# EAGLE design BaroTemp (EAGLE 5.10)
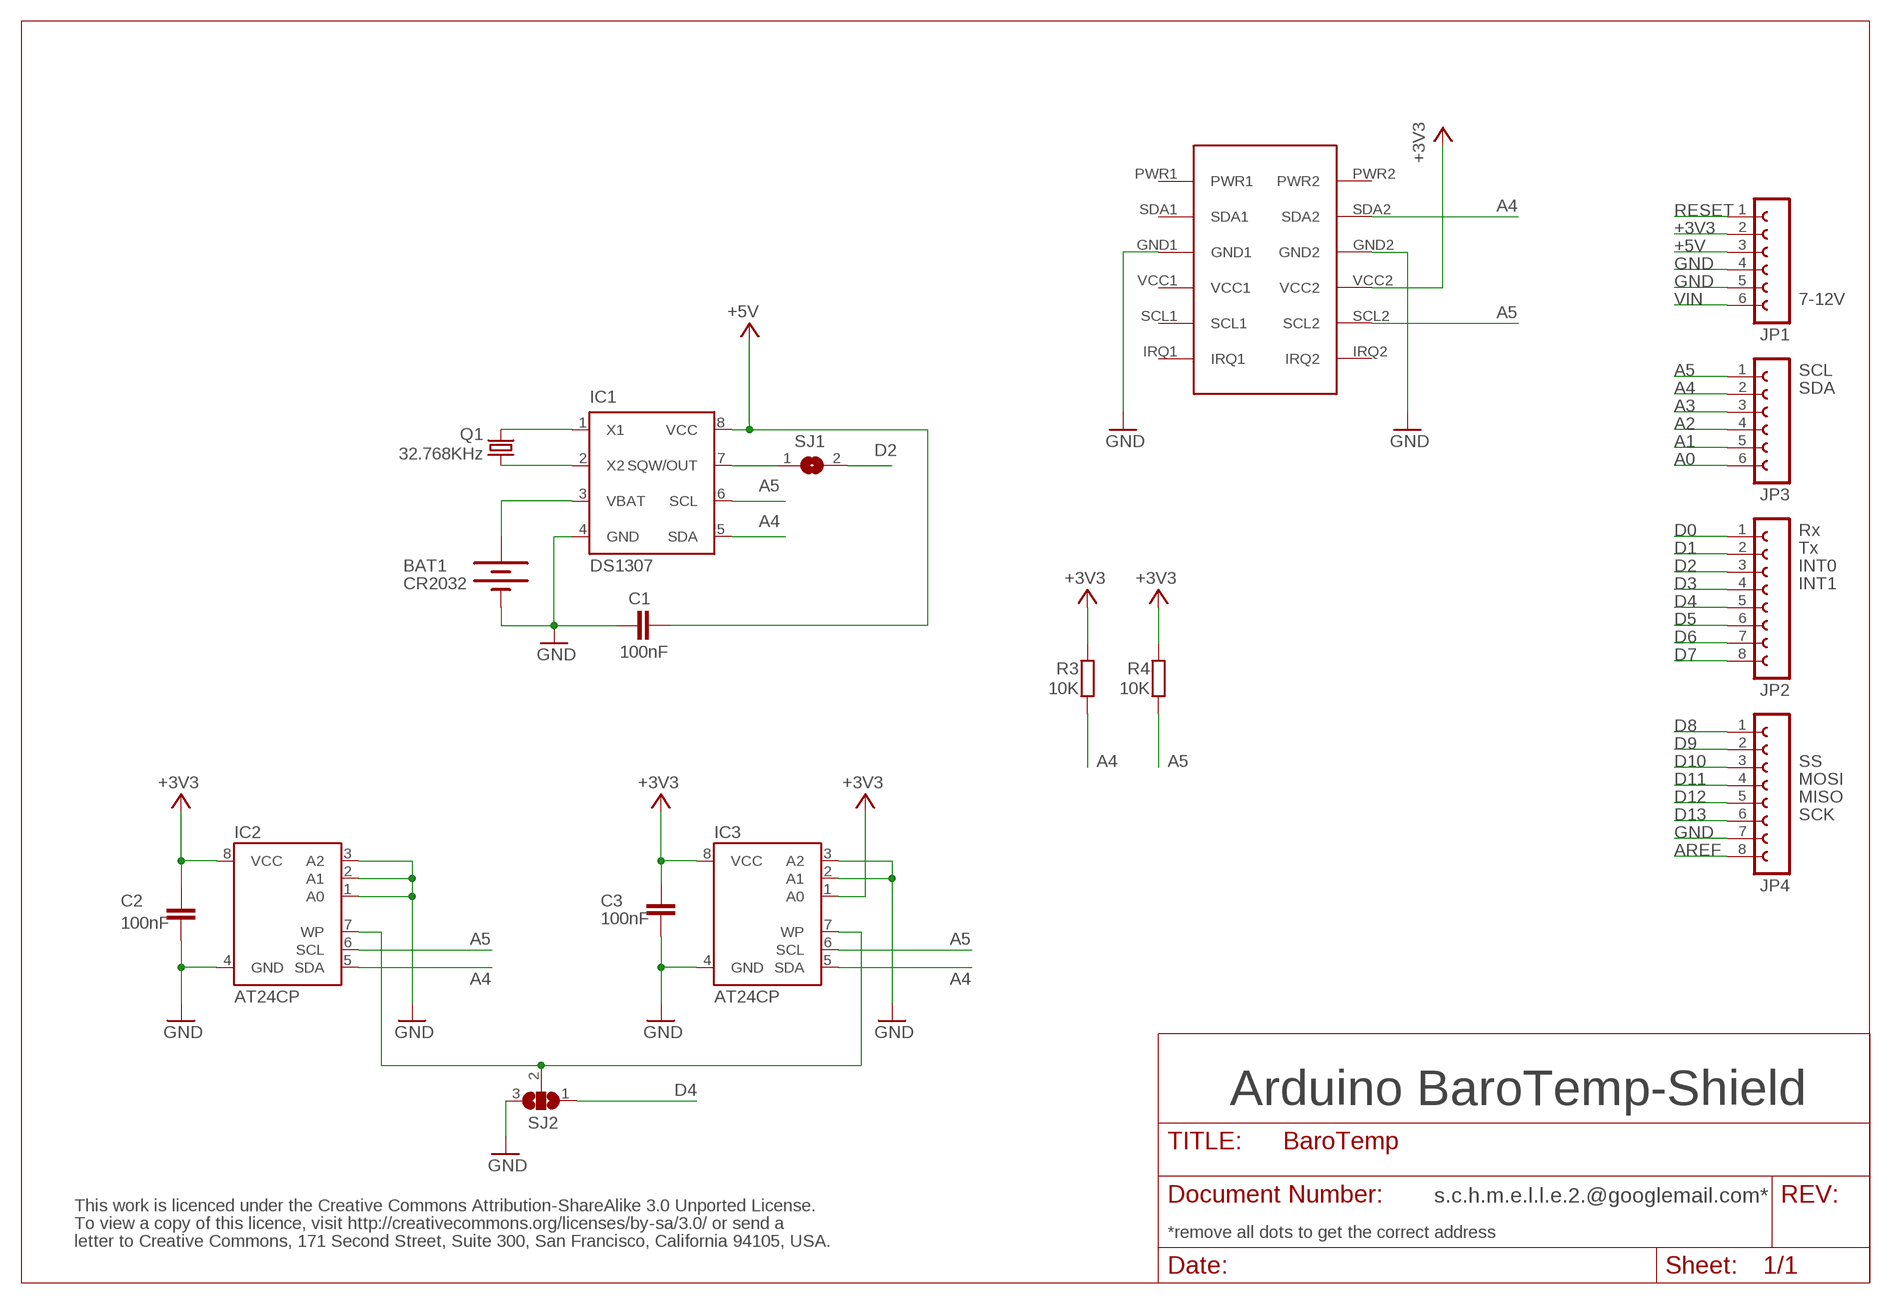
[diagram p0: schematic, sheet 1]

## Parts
BAT1  CR2032  BATTERY20PTH  [BATTCOM_20MM_PTH]
C1  100nF  C-EU050-025X075  [C050-025X075]
C2  100nF  C-EU050-025X075  [C050-025X075]
C3  100nF  C-EU050-025X075  [C050-025X075]
IC1  DS1307  [DIL08]
IC2  AT24CP  [DIL08]
IC3  AT24CP  [DIL08]
JP1  FE06-1  [FE06]
JP2  FE08-1  [FE08]
JP3  FE06-1  [FE06]
JP4  FE08-1  [FE08]
Q1  32.768KHz  CRYSTALTC26V  [TC26V]
R3  10K  R-EU_0207/10  [0207/10]
R4  10K  R-EU_0207/10  [0207/10]
SJ1  SJ  [SJ]
SJ2  SJ2W  [SJ_2]
U$1  PRESSURE_PLUG  [BMP085-BO]

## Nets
+3V3: C2.2 C3.2 IC2.8(VCC) IC3.1(A0) IC3.8(VCC) JP1.2 R3.2 R4.2 U$1.VCC2
+5V: C1.2 IC1.8(VCC) JP1.3
A0: JP3.6
A1: JP3.5
A2: JP3.4
A3: JP3.3
A4: IC1.5(SDA) IC2.5(SDA) IC3.5(SDA) JP3.2 R3.1 U$1.SDA2
A5: IC1.6(SCL) IC2.6(SCL) IC3.6(SCL) JP3.1 R4.1 U$1.SCL2
AREF: JP4.8
D0: JP2.1
D1: JP2.2
D2: JP2.3 SJ1.2
D3: JP2.4
D4: JP2.5 SJ2.1
D5: JP2.6
D6: JP2.7
D7: JP2.8
D8: JP4.1
D9: JP4.2
D10: JP4.3
D11: JP4.4
D12: JP4.5
D13: JP4.6
GND: BAT1.2(-) C1.1 C2.1 C3.1 IC1.4(GND) IC2.1(A0) IC2.2(A1) IC2.3(A2) IC2.4(GND) IC3.2(A1) IC3.3(A2) IC3.4(GND) JP1.4 JP1.5 JP4.7 SJ2.3 U$1.GND1 U$1.GND2
N$1: BAT1.1(+) IC1.3(VBAT)
N$3: IC2.7(WP) IC3.7(WP) SJ2.2
N$4: IC1.1(X1) Q1.2
N$6: IC1.2(X2) Q1.1
N$285: IC1.7(SQW/OUT) SJ1.1
RESET: JP1.1
VIN: JP1.6
Unconnected: U$1.IRQ1 U$1.IRQ2 U$1.SCL1 U$1.SDA1

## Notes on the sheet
- 7-12V
- SCL
- SDA
- Rx
- Tx
- INT0
- INT1
- SS
- MOSI
- MISO
- SCK
- Arduino BaroTemp-Shield
- s.c.h.m.e.l.l.e.2.@googlemail.com*
- This work is licenced under the Creative Commons Attribution-ShareAlike 3.0 Unported License.
- To view a copy of this licence, visit http://creativecommons.org/licenses/by-sa/3.0/ or send a
- *remove all dots to get the correct address
- letter to Creative Commons, 171 Second Street, Suite 300, San Francisco, California 94105, USA.

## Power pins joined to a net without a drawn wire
PWR1: U$1.PWR1
PWR2: U$1.PWR2
VCC1: U$1.VCC1

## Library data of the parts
BAT1 = SparkFun:BATTERY: Battery Holders
C1-C3 = resistor:C-EU: CAPACITOR, European symbol
IC1 = Peter-Privat:DS1307: I2C Serial RTC w/56 bytes battery backed RAM
IC2 IC3 = atmel:AT24C*: 2-wire serial EEPROM
JP1 JP3 = con-lsta:FE06-1: FEMALE HEADER
JP2 JP4 = con-lsta:FE08-1: FEMALE HEADER
Q1 = crystal:CRYSTAL: CRYSTAL
R3 R4 = resistor:R-EU_: RESISTOR, European symbol
SJ1 = jumper:SJ: SMD solder JUMPER
SJ2 = jumper:SJ2W: SMD solder JUMPER
U$1 = Peter-Privat:PRESSURE_PLUG: BMP085 Breakout Board von http://shop.jeelabs.com/products/pressure-plug

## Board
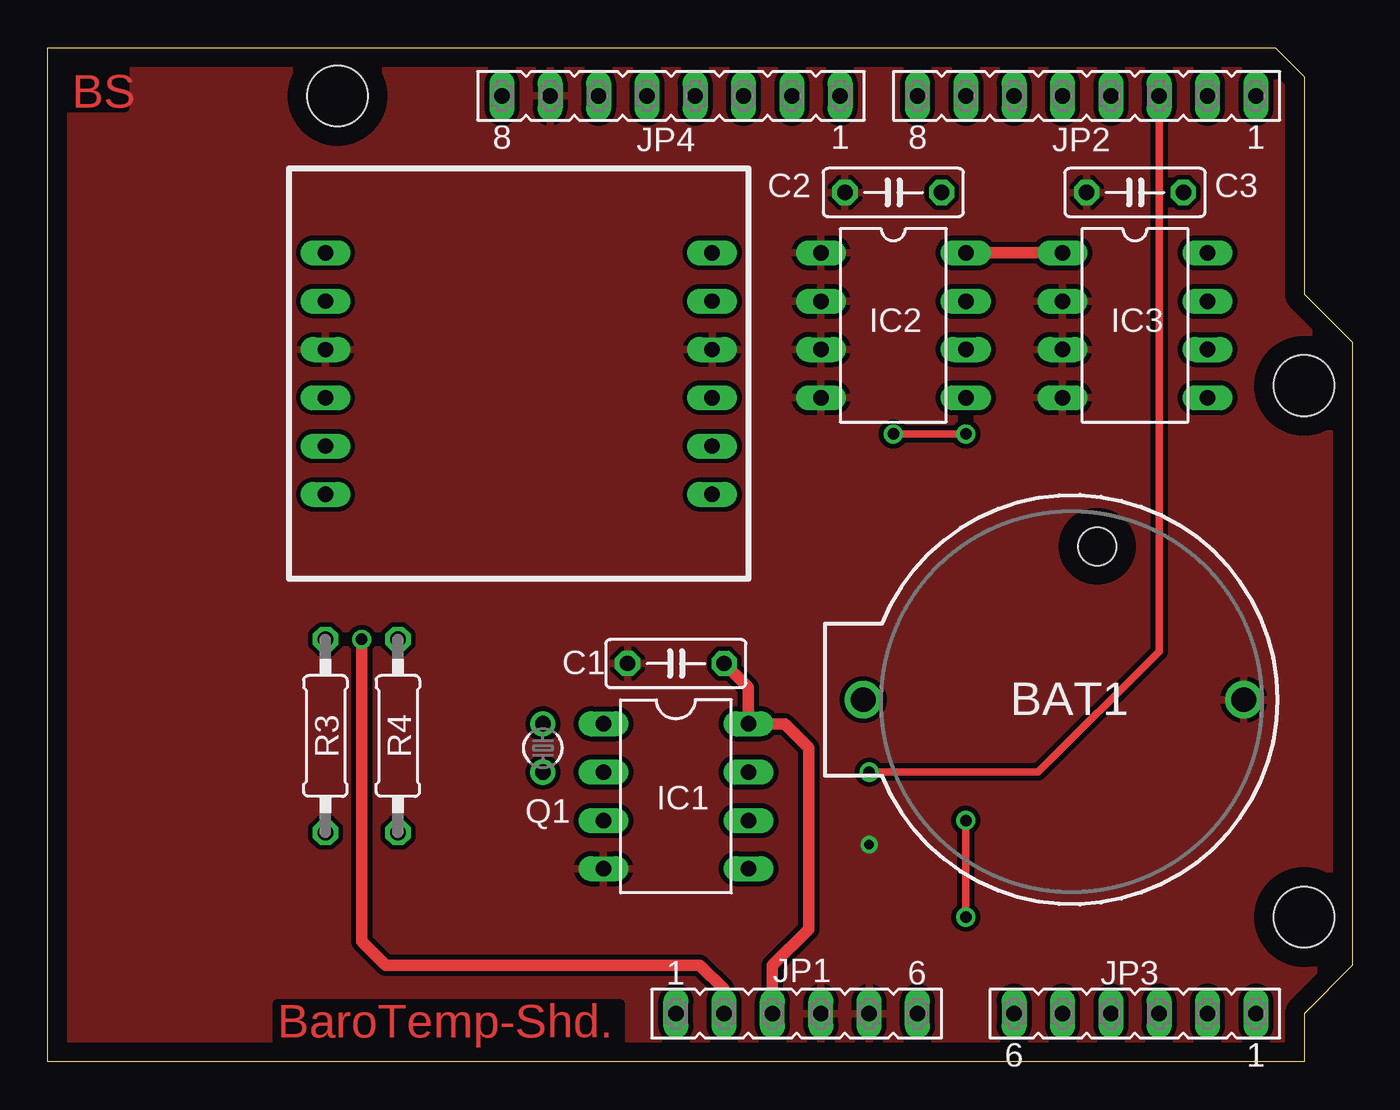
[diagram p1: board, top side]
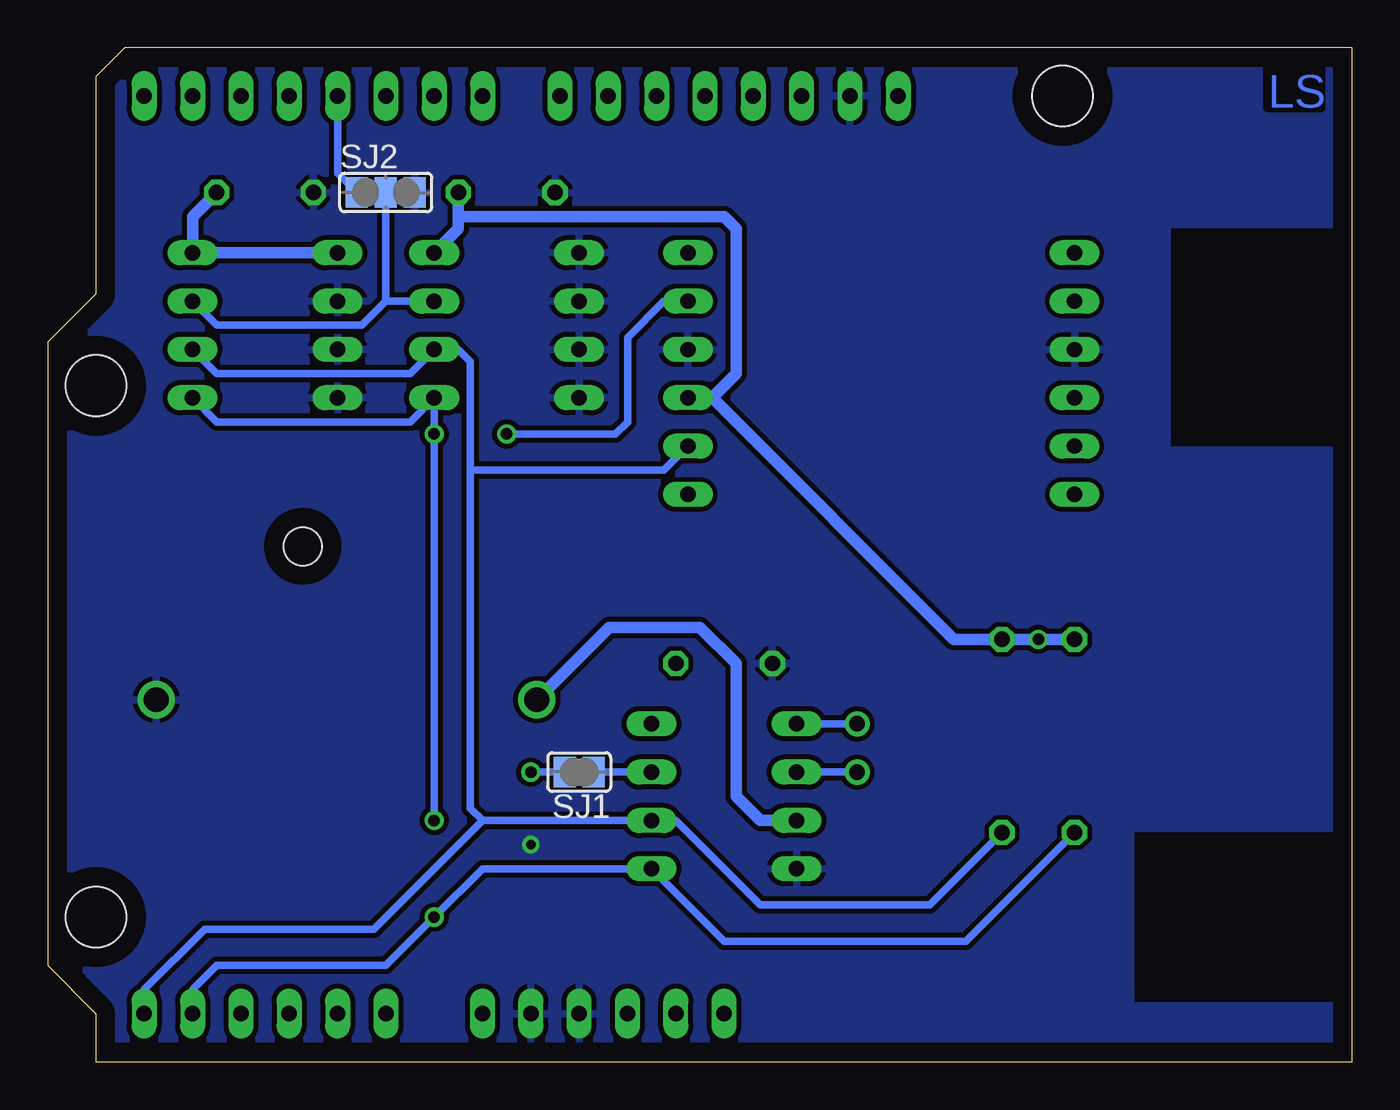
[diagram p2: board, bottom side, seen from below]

Size 68.58 x 53.34 mm. Coordinates in mm from the lower left corner, seen from the top.
Outline: 0,0 0,53.34 64.52,53.34 66.04,51.82 66.04,40.39 68.58,37.85 68.58,5.08 66.04,2.54 66.04,0 0,0
Copper layers (1*16): Top 0.035mm / dielectric 1.5mm / Bottom 0.035mm
Design rules "Bilex DRU": minimum track width 10mil, minimum drill 24mil, track to track 10mil, track to pad 10mil, pad to pad 10mil, via to via 10mil, smd to smd 10mil, copper to edge 40mil, drill to drill 8mil, minimum pad ring 10mil, minimum via ring 8mil, stop-mask expansion 4mil, vias tented up to drill 0mil, thermal gap 10mil
Holes 3.2 mm at 15.24,50.8 66.04,35.56 66.04,7.62
Holes 2 mm at 55.17,27.11
tKeepout: area 0,32.4 to 9.5,43.8; area 0,3.2 to 11.4,12.1
bKeepout: area 0,32.4 to 9.5,43.8; area 0,32.4 to 9.5,43.8; area 0,3.2 to 11.4,12.1
bRestrict: area 0,32.4 to 9.5,43.8; area 0,32.4 to 9.5,43.8; area 0,3.2 to 11.4,12.1

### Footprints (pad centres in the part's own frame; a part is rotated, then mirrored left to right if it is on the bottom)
BATTCOM_20MM_PTH = drill 1.3 round: 1 20,0; 2 0,0
C050-025X075 = drill 0.813 octagon: 1 -2.54,0; 2 2.54,0
DIL08 = drill 0.813 long: 1 -3.81,-3.81; 2 -1.27,-3.81; 3 1.27,-3.81; 4 3.81,-3.81; 5 3.81,3.81; 6 1.27,3.81; 7 -1.27,3.81; 8 -3.81,3.81
FE06 = drill 0.813 long: 1 -6.35,0; 2 -3.81,0; 3 -1.27,0; 4 1.27,0; 5 3.81,0; 6 6.35,0
FE08 = drill 0.813 long: 1 -8.89,0; 2 -6.35,0; 3 -3.81,0; 4 -1.27,0; 5 1.27,0; 6 3.81,0; 7 6.35,0; 8 8.89,0
TC26V = drill 0.813 round: 1 -1.27,0; 2 1.27,0
0207/10 = drill 0.813 octagon: 1 -5.08,0; 2 5.08,0
SJ = smd 1.168 x 1.6: 1 -0.762,0; 2 0.762,0
SJ_2 = smd 1.168 x 1.6: 1 -1.524,0; 2 0,0; 3 1.524,0
BMP085-BO = drill 0.8 long: GND1 -10.16,1.27; GND2 10.16,1.27; IRQ1 -10.16,-6.35; IRQ2 10.16,-6.35; PWR1 -10.16,6.35; PWR2 10.16,6.35; SCL1 -10.16,-3.81; SCL2 10.16,-3.81; SDA1 -10.16,3.81; SDA2 10.16,3.81; VCC1 -10.16,-1.27; VCC2 10.16,-1.27

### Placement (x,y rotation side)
BAT1  62.87,19.05 180 top
C1  33.02,20.95 0 top
C2  44.45,45.72 0 top
C3  57.15,45.72 0 top
IC1  33.02,13.97 270 top
IC2  44.45,38.73 270 top
IC3  57.15,38.73 270 top
JP1  39.37,2.54 0 top
JP2  54.61,50.8 180 top
JP3  57.15,2.54 180 top
JP4  32.77,50.8 180 top
Q1  26.04,16.51 90 top
R3  14.61,17.14 90 top
R4  18.41,17.14 90 top
SJ1  40.64,15.24 180 bottom
SJ2  50.8,45.72 0 bottom
U$1  24.77,36.2 0 top

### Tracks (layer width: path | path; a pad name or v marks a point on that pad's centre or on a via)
+3V3  (via drill 0.6)
  Top 0.61: IC2.8 IC3.1 | JP1.2 35.56,3.81 34.29,5.08 17.78,5.08 16.51,6.35 v16.51,22.23
  Bottom 0.61: 46.99,44.45 46.99,43.81 IC2.8 | 46.99,44.45 C2.2 | C3.2 60.96,44.45 IC3.8 IC3.1 | 33.66,34.92 32.38,36.2 32.38,43.81 33.02,44.45 46.99,44.45 | 33.66,34.92 20.95,22.23 R4.2 v16.51,22.23 R3.2 | 33.66,34.92 U$1.VCC2
+5V
  Top 0.61: C1.2 36.83,19.68 IC1.8 38.73,17.78 40.01,16.51 40.01,6.99 38.1,5.08 JP1.3
A4  (via drill 0.6)
  Top 0.406: v48.26,33.02 v44.45,33.02 | v48.26,7.62 v48.26,12.7
  Bottom 0.406: JP3.2 60.96,3.81 59.69,5.08 50.8,5.08 v48.26,7.62 45.72,10.16 IC1.5 33.02,6.35 20.32,6.35 R3.1 | IC3.5 59.69,33.66 49.53,33.66 IC2.5 v48.26,33.02 v48.26,12.7 | U$1.SDA2 36.2,40.01 38.1,38.1 38.1,33.66 38.73,33.02 v44.45,33.02
A5
  Bottom 0.406: JP3.1 63.5,3.81 60.33,6.99 51.44,6.99 45.72,12.7 | 45.72,12.7 IC1.6 35.56,12.7 31.11,8.26 22.23,8.26 R4.1 | IC3.6 59.69,36.2 49.53,36.2 IC2.6 46.99,37.47 46.35,36.83 46.35,31.11 | 45.72,12.7 46.35,13.34 46.35,31.11 | U$1.SCL2 36.2,31.11 46.35,31.11
D2  (via drill 0.6)
  Top 0.406: v43.18,15.24 52.07,15.24 58.42,21.59 JP2.3
  Bottom 0.406: SJ1.2 v43.18,15.24
D4
  Bottom 0.406: SJ2.1 53.34,46.74 JP2.5
GND  (via drill 0.5)
  other vias: 43.18,11.43
  pour Top: 0,0 0,53.34 64.52,53.34 66.04,51.82 66.04,40.39 68.58,37.85 68.58,5.08 66.04,2.54 66.04,0
  pour Bottom: 0,0 0,53.34 64.52,53.34 66.04,51.82 66.04,40.39 68.58,37.85 68.58,5.08 66.04,2.54 66.04,0
N$1
  Bottom 0.61: BAT1.1 39.05,22.86 34.29,22.86 32.38,20.95 32.38,13.97 31.11,12.7 IC1.3
N$3
  Bottom 0.406: IC2.7 50.8,40.01 | IC3.7 59.69,38.73 52.07,38.73 50.8,40.01 | 50.8,40.01 SJ2.2
N$4
  Bottom 0.406: Q1.2 IC1.1
N$6
  Bottom 0.406: Q1.1 IC1.2
N$285
  Bottom 0.406: IC1.7 SJ1.1

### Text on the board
Top: BS | BaroTemp-Shd.
Bottom: LS
Document: This work is licenced under the Creative Commons Attribution-ShareAlike 3.0 Unported License. | To view a copy of this licence, visit http://creativecommons.org/licenses/by-sa/3.0/ or send a | letter to Creative Commons, 171 Second Street, Suite 300, San Francisco, California 94105, USA.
